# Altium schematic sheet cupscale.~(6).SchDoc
size A
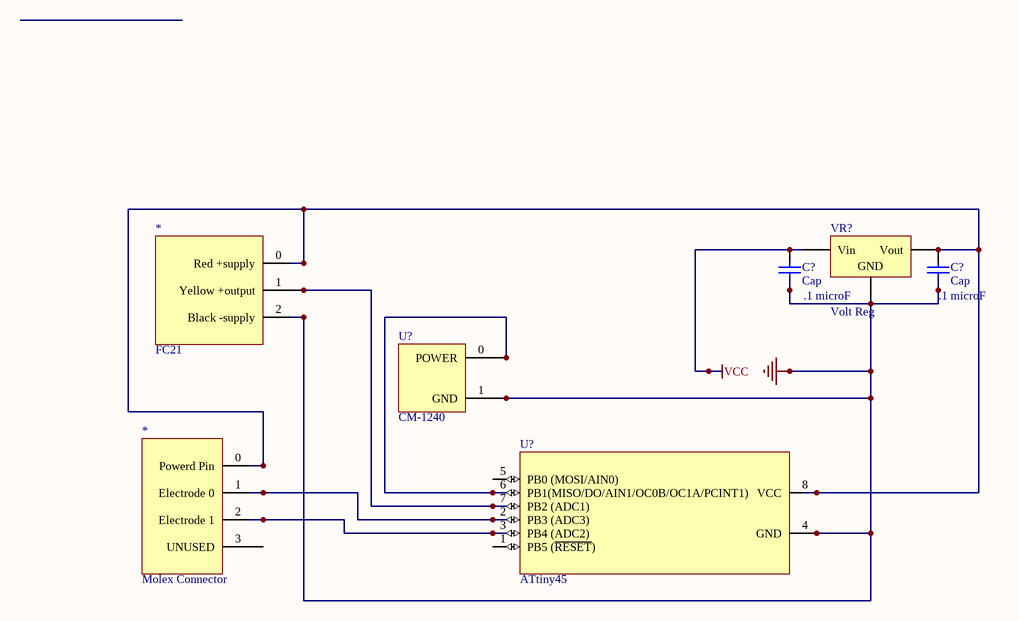
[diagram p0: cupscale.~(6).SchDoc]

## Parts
(Parts that share a designator on the sheet are numbered #1, #2 ... from top to bottom, then left to right.)
*#1  FC21  [FC21-Load Cell]
*#2  Molex Connector  [4 PIN Molex]
C?#1  Cap  value .1 microF  [VP32-3.2]
C?#2  Cap  value .1 microF  [VP32-3.2]
U?#1  CM-1240  [CMI-1240-buzzer]
U?#2  ATtiny45  [8S2_M]
VR?  Volt Reg  [SOT-23]

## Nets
GND: *#1.2(Black_-supply) C?#1.1 C?#2.1 U?#1.1(GND) U?#2.4(GND) VR?.3(GND)
VCC: C?#1.2 VR?.2(Vin)
Net*#1_0: *#1.0(Red_+supply) *#2.0(Powerd_Pin) C?#2.2 U?#2.8(VCC) VR?.1(Vout)
Net*#1_1: *#1.1(Yellow_+output) U?#2.7(PB2_(ADC1))
Net*#2_1: *#2.1(Electrode_0) U?#2.2(PB3_(ADC3))
Net*#2_2: *#2.2(Electrode_1) U?#2.3(PB4_(ADC2))
NetU?#1_0: U?#1.0(POWER) U?#2.6(PB1(MISO/DO/AIN1/OC0B/OC1A/PCINT1))

Not connected (* = marked no-connect by the designer): *#2 3(UNUSED); U?#2 1(PB5_(~{RESET})) 5(PB0_(MOSI/AIN0))

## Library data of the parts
C?#1 C?#2 = Cap: Capacitor
U?#1 = CMI-1240
U?#2 = ATtiny45: 8-Bit AVR Microcontroller with 1K Byte of Flash Memory
VR? = Volt Reg: Voltage Regulator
